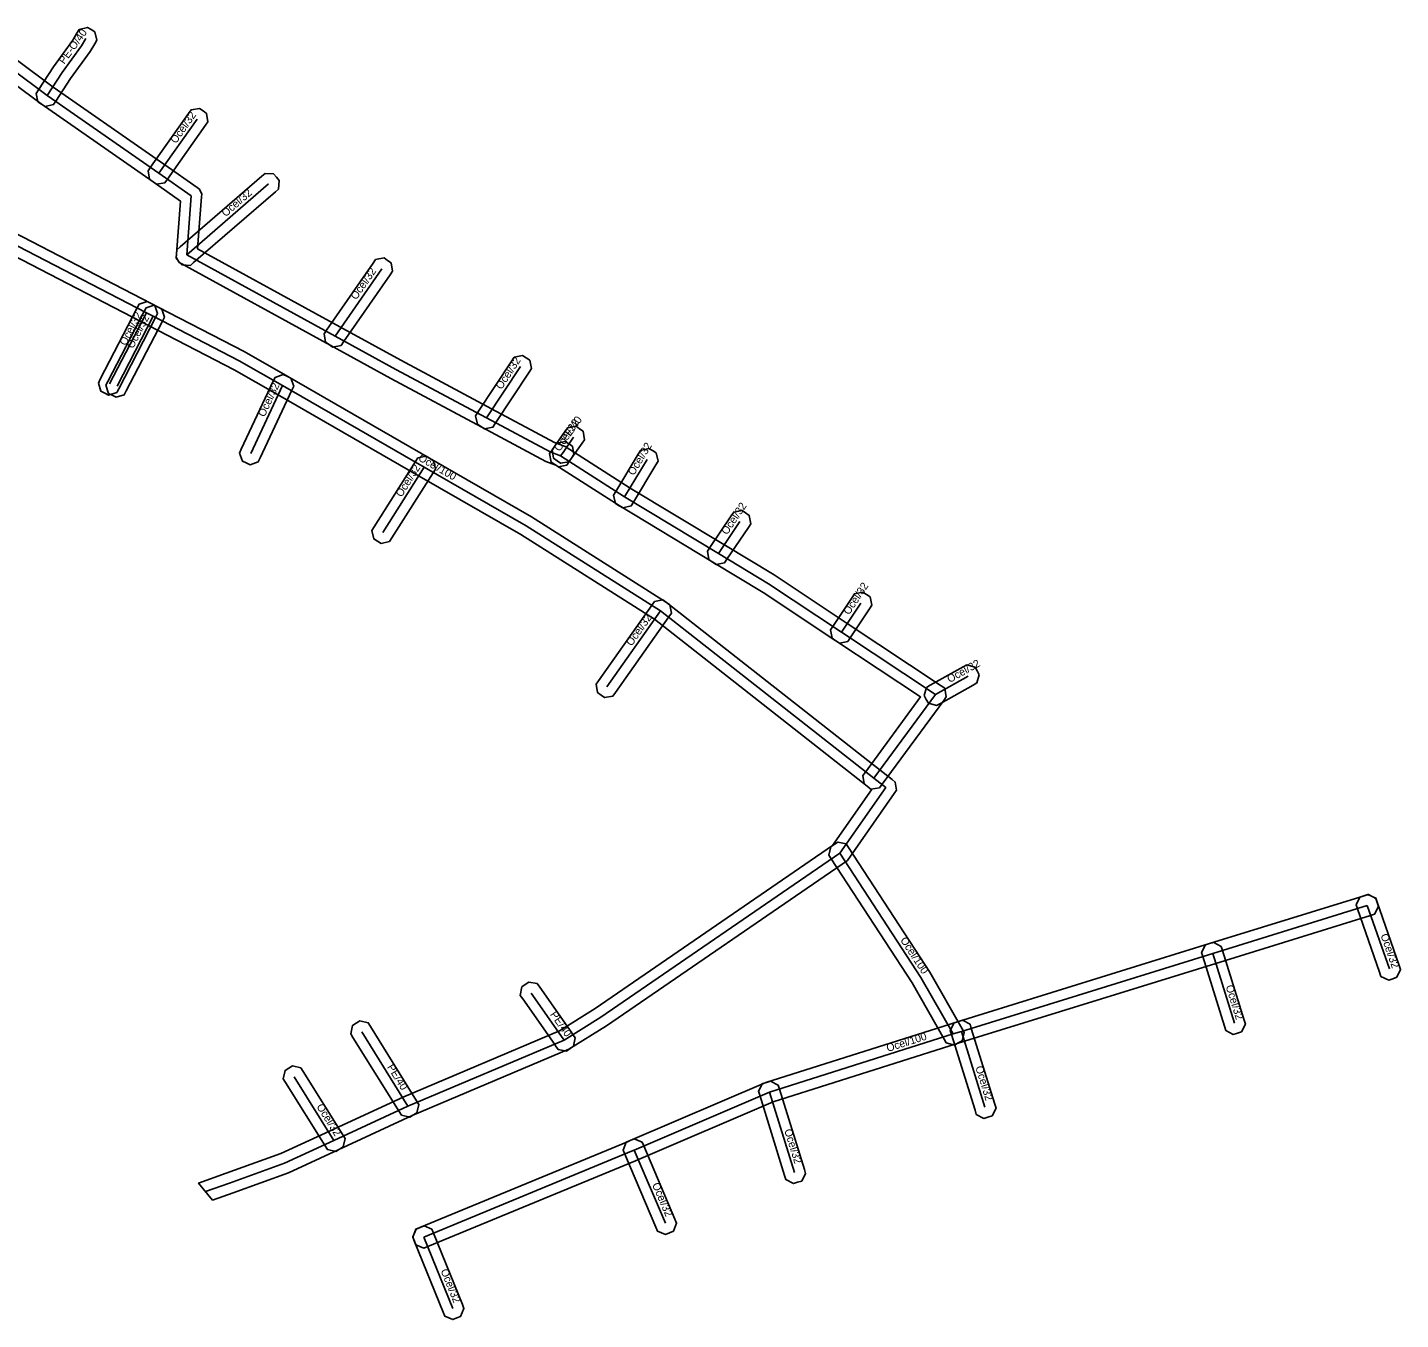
# Model space of a CAD drawing. Extents: x -588157 to -587884, y -1179022 to -1178805.
# Drawn here: x -588016.9 to -587884.2, y -1179022.3 to -1178897.4 of the extents above; entities that cross this region are included whole.
import ezdxf

# ---------------------------------------------------------------- set-up
doc = ezdxf.new("R2010")
doc.units = 0
for name, color, linetype in [('1', 7, 'Continuous'), ('14', 7, 'Continuous'), ('20', 7, 'Continuous')]:
    doc.layers.add(name, color=color, linetype=linetype)

msp = doc.modelspace()

# ---------------------------------------------------------------- linework, layer by layer
at = {"layer": '1'}
for points in [[(-588016.024, -1178903.821), (-588015.798, -1178903.474), (-588014.345, -1178901.244), (-588012.486, -1178898.669), (-588012.087, -1178898.006), (-588011.874, -1178897.651), (-588011.071, -1178897.45), (-588010.716, -1178897.663), (-588010.361, -1178897.876), (-588010.16, -1178898.679), (-588010.373, -1178899.034), (-588010.814, -1178899.771), (-588012.695, -1178902.376), (-588014.122, -1178904.566), (-588014.348, -1178904.913), (-588015.159, -1178905.084), (-588015.506, -1178904.858), (-588015.853, -1178904.632)], [(-588005.216, -1178911.301), (-588004.977, -1178910.963), (-588001.297, -1178905.753), (-588001.058, -1178905.415), (-588000.241, -1178905.274), (-587999.903, -1178905.513), (-587999.565, -1178905.752), (-587999.424, -1178906.569), (-587999.663, -1178906.907), (-588003.343, -1178912.117), (-588003.582, -1178912.455), (-588004.399, -1178912.596), (-588004.737, -1178912.357), (-588005.075, -1178912.118)], [(-588002.438, -1178918.935), (-588002.125, -1178918.664), (-587994.225, -1178911.824), (-587993.912, -1178911.553), (-587993.085, -1178911.612), (-587992.814, -1178911.925), (-587992.543, -1178912.238), (-587992.602, -1178913.065), (-587992.915, -1178913.336), (-588000.815, -1178920.176), (-588001.128, -1178920.447), (-588001.955, -1178920.388), (-588002.226, -1178920.075), (-588002.497, -1178919.762)], [(-587988.208, -1178927.049), (-587987.971, -1178926.709), (-587983.461, -1178920.219), (-587983.225, -1178919.879), (-587982.409, -1178919.732), (-587982.069, -1178919.969), (-587981.729, -1178920.205), (-587981.582, -1178921.021), (-587981.819, -1178921.361), (-587986.329, -1178927.851), (-587986.565, -1178928.191), (-587987.381, -1178928.338), (-587987.721, -1178928.101), (-587988.061, -1178927.865)], [(-588010.018, -1178931.819), (-588009.828, -1178931.451), (-588006.268, -1178924.561), (-588006.078, -1178924.193), (-588005.289, -1178923.942), (-588004.921, -1178924.132), (-588004.553, -1178924.322), (-588004.302, -1178925.111), (-588004.492, -1178925.479), (-588008.052, -1178932.369), (-588008.242, -1178932.737), (-588009.031, -1178932.988), (-588009.399, -1178932.798), (-588009.767, -1178932.608)], [(-588009.289, -1178932.027), (-588009.098, -1178931.66), (-588005.598, -1178924.91), (-588005.407, -1178924.542), (-588004.617, -1178924.291), (-588004.25, -1178924.482), (-588003.882, -1178924.673), (-588003.631, -1178925.463), (-588003.822, -1178925.83), (-588007.322, -1178932.58), (-588007.513, -1178932.948), (-588008.303, -1178933.199), (-588008.67, -1178933.008), (-588009.038, -1178932.817)], [(-587973.563, -1178934.986), (-587973.335, -1178934.64), (-587970.065, -1178929.67), (-587969.838, -1178929.324), (-587969.026, -1178929.157), (-587968.68, -1178929.385), (-587968.334, -1178929.612), (-587968.167, -1178930.424), (-587968.395, -1178930.77), (-587971.665, -1178935.74), (-587971.892, -1178936.086), (-587972.704, -1178936.253), (-587973.05, -1178936.025), (-587973.396, -1178935.798)], [(-587996.381, -1178938.591), (-587996.205, -1178938.216), (-587993.125, -1178931.646), (-587992.949, -1178931.271), (-587992.171, -1178930.989), (-587991.796, -1178931.165), (-587991.421, -1178931.341), (-587991.139, -1178932.119), (-587991.315, -1178932.494), (-587994.395, -1178939.064), (-587994.571, -1178939.439), (-587995.349, -1178939.721), (-587995.724, -1178939.545), (-587996.099, -1178939.369)], [(-587966.176, -1178938.282), (-587965.937, -1178937.944), (-587964.907, -1178936.484), (-587964.668, -1178936.145), (-587963.852, -1178936.004), (-587963.514, -1178936.243), (-587963.175, -1178936.482), (-587963.034, -1178937.298), (-587963.273, -1178937.636), (-587964.303, -1178939.096), (-587964.542, -1178939.435), (-587965.358, -1178939.576), (-587965.696, -1178939.337), (-587966.035, -1178939.098)], [(-587966.41, -1178938.643), (-587966.178, -1178938.3), (-587965.948, -1178937.96), (-587965.716, -1178937.617), (-587964.903, -1178937.46), (-587964.56, -1178937.692), (-587964.217, -1178937.924), (-587964.06, -1178938.737), (-587964.292, -1178939.08), (-587964.522, -1178939.42), (-587964.754, -1178939.763), (-587965.567, -1178939.92), (-587965.91, -1178939.688), (-587966.253, -1178939.456)], [(-587983.587, -1178946.075), (-587983.365, -1178945.725), (-587979.365, -1178939.415), (-587979.143, -1178939.065), (-587978.335, -1178938.883), (-587977.985, -1178939.105), (-587977.635, -1178939.327), (-587977.453, -1178940.135), (-587977.675, -1178940.485), (-587981.675, -1178946.795), (-587981.897, -1178947.145), (-587982.705, -1178947.327), (-587983.055, -1178947.105), (-587983.405, -1178946.883)], [(-587960.24, -1178942.658), (-587960.026, -1178942.303), (-587957.846, -1178938.693), (-587957.632, -1178938.338), (-587956.828, -1178938.14), (-587956.473, -1178938.354), (-587956.118, -1178938.568), (-587955.92, -1178939.372), (-587956.134, -1178939.727), (-587958.314, -1178943.337), (-587958.528, -1178943.692), (-587959.332, -1178943.89), (-587959.687, -1178943.676), (-587960.042, -1178943.462)], [(-587951.171, -1178948.073), (-587950.939, -1178947.73), (-587948.859, -1178944.65), (-587948.627, -1178944.307), (-587947.813, -1178944.149), (-587947.47, -1178944.381), (-587947.127, -1178944.613), (-587946.969, -1178945.427), (-587947.201, -1178945.77), (-587949.281, -1178948.85), (-587949.513, -1178949.193), (-587950.327, -1178949.351), (-587950.67, -1178949.119), (-587951.013, -1178948.887)], [(-587939.272, -1178955.682), (-587939.043, -1178955.337), (-587937.183, -1178952.537), (-587936.954, -1178952.192), (-587936.142, -1178952.028), (-587935.797, -1178952.257), (-587935.452, -1178952.486), (-587935.288, -1178953.298), (-587935.517, -1178953.643), (-587937.377, -1178956.443), (-587937.606, -1178956.788), (-587938.418, -1178956.952), (-587938.763, -1178956.723), (-587939.108, -1178956.494)], [(-587961.926, -1178960.932), (-587961.687, -1178960.594), (-587956.517, -1178953.264), (-587956.278, -1178952.925), (-587955.462, -1178952.784), (-587955.124, -1178953.023), (-587954.785, -1178953.262), (-587954.644, -1178954.078), (-587954.883, -1178954.416), (-587960.053, -1178961.746), (-587960.292, -1178962.085), (-587961.108, -1178962.226), (-587961.446, -1178961.987), (-587961.785, -1178961.748)], [(-587929.99, -1178961.239), (-587929.628, -1178961.037), (-587926.458, -1178959.267), (-587926.096, -1178959.065), (-587925.299, -1178959.29), (-587925.097, -1178959.652), (-587924.895, -1178960.014), (-587925.12, -1178960.811), (-587925.482, -1178961.013), (-587928.652, -1178962.783), (-587929.014, -1178962.985), (-587929.811, -1178962.76), (-587930.013, -1178962.398), (-587930.215, -1178962.036)], [(-587928.083, -1178995.596), (-587928.288, -1178995.236), (-587931.394, -1178989.801), (-587939.198, -1178977.795), (-587939.424, -1178977.448), (-587939.252, -1178976.638), (-587938.905, -1178976.412), (-587938.558, -1178976.186), (-587937.748, -1178976.358), (-587937.522, -1178976.705), (-587929.686, -1178988.759), (-587926.552, -1178994.244), (-587926.347, -1178994.604), (-587926.564, -1178995.403), (-587926.924, -1178995.608), (-587927.284, -1178995.813)], [(-587979.325, -1179013.604), (-587978.942, -1179013.446), (-587958.904, -1179005.161), (-587958.64, -1179005.043), (-587945.509, -1178999.431), (-587927.72, -1178993.786), (-587926.917, -1178993.535), (-587902.636, -1178986.005), (-587887.696, -1178981.375), (-587887.3, -1178981.252), (-587886.568, -1178981.638), (-587886.445, -1178982.034), (-587886.322, -1178982.43), (-587886.708, -1178983.162), (-587887.104, -1178983.285), (-587902.044, -1178987.915), (-587926.323, -1178995.445), (-587927.12, -1178995.694), (-587944.811, -1179001.309), (-587957.84, -1179006.877), (-587958.116, -1179006.999), (-587978.178, -1179015.294), (-587978.561, -1179015.452), (-587979.326, -1179015.135), (-587979.484, -1179014.752), (-587979.642, -1179014.369)], [(-587886.592, -1178981.61), (-587886.456, -1178982.001), (-587884.326, -1178988.121), (-587884.19, -1178988.512), (-587884.55, -1178989.258), (-587884.941, -1178989.394), (-587885.332, -1178989.53), (-587886.078, -1178989.17), (-587886.214, -1178988.779), (-587888.344, -1178982.659), (-587888.48, -1178982.268), (-587888.12, -1178981.522), (-587887.729, -1178981.386), (-587887.338, -1178981.25)], [(-587901.508, -1178986.268), (-587901.385, -1178986.664), (-587899.295, -1178993.404), (-587899.172, -1178993.8), (-587899.558, -1178994.532), (-587899.954, -1178994.655), (-587900.35, -1178994.778), (-587901.082, -1178994.392), (-587901.205, -1178993.996), (-587903.295, -1178987.256), (-587903.418, -1178986.86), (-587903.032, -1178986.128), (-587902.636, -1178986.005), (-587902.24, -1178985.882)], [(-587967.607, -1178989.867), (-587967.37, -1178990.207), (-587964.279, -1178994.629), (-587964.188, -1178994.761), (-587963.952, -1178995.101), (-587964.101, -1178995.916), (-587964.441, -1178996.152), (-587964.781, -1178996.388), (-587965.596, -1178996.239), (-587965.832, -1178995.899), (-587965.921, -1178995.771), (-587969.01, -1178991.353), (-587969.247, -1178991.013), (-587969.103, -1178990.197), (-587968.763, -1178989.96), (-587968.423, -1178989.723)], [(-587980.741, -1179002.6), (-587980.959, -1179002.248), (-587985.419, -1178995.068), (-587985.638, -1178994.716), (-587985.45, -1178993.909), (-587985.098, -1178993.691), (-587984.746, -1178993.472), (-587983.939, -1178993.66), (-587983.721, -1178994.012), (-587979.261, -1179001.192), (-587979.042, -1179001.544), (-587979.23, -1179002.351), (-587979.582, -1179002.569), (-587979.934, -1179002.788)], [(-587925.788, -1178993.798), (-587925.665, -1178994.194), (-587923.395, -1179001.524), (-587923.272, -1179001.92), (-587923.658, -1179002.652), (-587924.054, -1179002.775), (-587924.45, -1179002.898), (-587925.182, -1179002.512), (-587925.305, -1179002.116), (-587927.575, -1178994.786), (-587927.698, -1178994.39), (-587927.312, -1178993.658), (-587926.916, -1178993.535), (-587926.52, -1178993.412)], [(-587990.462, -1178998.009), (-587990.242, -1178998.36), (-587986.402, -1179004.5), (-587986.182, -1179004.851), (-587986.369, -1179005.658), (-587986.72, -1179005.878), (-587987.071, -1179006.098), (-587987.878, -1179005.911), (-587988.098, -1179005.56), (-587991.938, -1178999.42), (-587992.158, -1178999.069), (-587991.971, -1178998.262), (-587991.62, -1178998.042), (-587991.269, -1178997.822)], [(-587944.328, -1178999.677), (-587944.205, -1179000.073), (-587941.795, -1179007.823), (-587941.672, -1179008.219), (-587942.057, -1179008.952), (-587942.453, -1179009.075), (-587942.849, -1179009.198), (-587943.582, -1179008.813), (-587943.705, -1179008.417), (-587946.115, -1179000.667), (-587946.238, -1179000.271), (-587945.853, -1178999.538), (-587945.457, -1178999.415), (-587945.061, -1178999.292)], [(-587957.483, -1179005.186), (-587957.32, -1179005.567), (-587954.3, -1179012.637), (-587954.138, -1179013.018), (-587954.446, -1179013.787), (-587954.827, -1179013.95), (-587955.208, -1179014.112), (-587955.977, -1179013.804), (-587956.14, -1179013.423), (-587959.16, -1179006.353), (-587959.322, -1179005.972), (-587959.014, -1179005.203), (-587958.633, -1179005.04), (-587958.252, -1179004.878)], [(-587977.788, -1179013.611), (-587977.633, -1179013.995), (-587974.843, -1179020.885), (-587974.688, -1179021.269), (-587975.011, -1179022.032), (-587975.395, -1179022.187), (-587975.779, -1179022.342), (-587976.542, -1179022.019), (-587976.697, -1179021.635), (-587979.487, -1179014.745), (-587979.642, -1179014.361), (-587979.319, -1179013.598), (-587978.935, -1179013.443), (-587978.551, -1179013.288)]]:
    msp.add_lwpolyline(points, close=True, dxfattribs=at)
for points in [[(-588017.966, -1178900.543), (-588014.376, -1178903.208), (-588003.586, -1178910.721), (-588000.472, -1178912.924), (-588000.257, -1178913.076), (-588000.033, -1178913.552), (-588000.053, -1178913.814), (-588000.425, -1178918.853), (-587986.669, -1178926.403), (-587980.794, -1178929.621), (-587972.028, -1178934.309), (-587965.957, -1178937.567), (-587964.901, -1178937.96), (-587958.642, -1178941.971), (-587949.593, -1178947.434), (-587944.715, -1178950.375), (-587937.657, -1178955.057), (-587928.587, -1178961.077), (-587928.23, -1178961.314), (-587928.155, -1178961.736), (-587928.081, -1178962.158), (-587928.335, -1178962.503), (-587934.295, -1178970.603), (-587934.54, -1178970.936), (-587935.359, -1178971.061), (-587935.693, -1178970.815), (-587936.026, -1178970.57), (-587936.151, -1178969.751), (-587935.905, -1178969.417), (-587930.568, -1178962.163), (-587938.763, -1178956.723), (-587945.785, -1178952.065), (-587950.627, -1178949.146), (-587959.698, -1178943.669), (-587965.799, -1178939.76), (-587966.783, -1178939.393), (-587972.972, -1178936.071), (-587981.746, -1178931.379), (-587987.631, -1178928.157), (-588001.951, -1178920.297), (-588002.209, -1178920.155), (-588002.489, -1178919.639), (-588002.467, -1178919.346), (-588002.089, -1178914.23), (-588004.734, -1178912.359), (-588015.544, -1178904.832), (-588019.14, -1178902.163)], [(-588020.06, -1178916.302), (-588004.919, -1178924.133), (-588004.249, -1178924.483), (-587995.931, -1178928.782), (-587991.721, -1178931.203), (-587978.021, -1178939.083), (-587968.173, -1178944.754), (-587955.122, -1178953.022), (-587934.481, -1178969.225), (-587933.319, -1178970.147), (-587933.008, -1178970.393), (-587932.893, -1178971.178), (-587933.121, -1178971.503), (-587937.644, -1178977.972), (-587960.922, -1178993.957), (-587964.547, -1178996.22), (-587979.705, -1179002.634), (-587986.83, -1179005.938), (-587991.64, -1179008.156), (-587997.002, -1179010.091), (-587998.987, -1179010.799), (-587998.993, -1179010.791), (-588000.331, -1179009.155), (-587997.678, -1179008.209), (-587992.4, -1179006.304), (-587987.67, -1179004.122), (-587980.515, -1179000.806), (-587965.473, -1178994.44), (-587962.018, -1178992.283), (-587939.076, -1178976.528), (-587935.299, -1178971.128), (-587935.719, -1178970.795), (-587956.278, -1178954.658), (-587969.207, -1178946.466), (-587979.019, -1178940.817), (-587992.719, -1178932.937), (-587996.889, -1178930.538), (-588005.171, -1178926.257), (-588005.841, -1178925.907), (-588020.98, -1178918.078)]]:
    msp.add_lwpolyline(points, dxfattribs=at)
at = {"layer": '14'}
for points in [[(-588014.96, -1178904.02), (-588013.52, -1178901.81), (-588011.65, -1178899.22), (-588011.23, -1178898.52)], [(-587935.1, -1178970.01), (-587929.14, -1178961.91), (-587938.21, -1178955.89), (-587945.25, -1178951.22), (-587950.11, -1178948.29), (-587959.17, -1178942.82), (-587965.35, -1178938.86), (-587966.37, -1178938.48), (-587972.5, -1178935.19), (-587981.27, -1178930.5), (-587987.15, -1178927.28), (-588001.47, -1178919.42), (-588001.05, -1178913.74), (-588004.16, -1178911.54), (-588014.96, -1178904.02), (-588018.553, -1178901.353)], [(-588004.16, -1178911.54), (-588000.48, -1178906.33)], [(-588001.47, -1178919.42), (-587993.57, -1178912.58)], [(-587999.659, -1179009.977), (-587997.34, -1179009.15), (-587992.02, -1179007.23), (-587987.25, -1179005.03), (-587980.11, -1179001.72), (-587965.01, -1178995.33), (-587961.47, -1178993.12), (-587938.36, -1178977.25), (-587933.94, -1178970.93), (-587935.1, -1178970.01), (-587955.7, -1178953.84), (-587968.69, -1178945.61), (-587978.52, -1178939.95), (-587992.22, -1178932.07), (-587996.41, -1178929.66), (-588004.71, -1178925.37), (-588005.38, -1178925.02), (-588020.52, -1178917.19)], [(-587987.15, -1178927.28), (-587982.64, -1178920.79)], [(-588008.94, -1178931.91), (-588005.38, -1178925.02)], [(-588008.21, -1178932.12), (-588004.71, -1178925.37)], [(-587972.5, -1178935.19), (-587969.23, -1178930.22)], [(-587995.3, -1178938.64), (-587992.22, -1178932.07)], [(-587965.12, -1178938.52), (-587964.09, -1178937.06)], [(-587965.35, -1178938.86), (-587965.12, -1178938.52)], [(-587982.52, -1178946.26), (-587978.52, -1178939.95)], [(-587959.17, -1178942.82), (-587956.99, -1178939.21)], [(-587950.11, -1178948.29), (-587948.03, -1178945.21)], [(-587938.21, -1178955.89), (-587936.35, -1178953.09)], [(-587960.87, -1178961.17), (-587955.7, -1178953.84)], [(-587929.14, -1178961.91), (-587925.97, -1178960.14)], [(-587927.42, -1178994.74), (-587930.54, -1178989.28), (-587938.36, -1178977.25)], [(-587978.56, -1179014.37), (-587958.51, -1179006.08), (-587958.24, -1179005.96), (-587945.16, -1179000.37), (-587927.42, -1178994.74), (-587926.62, -1178994.49), (-587902.34, -1178986.96), (-587887.4, -1178982.33)], [(-587887.4, -1178982.33), (-587885.27, -1178988.45)], [(-587902.34, -1178986.96), (-587900.25, -1178993.7)], [(-587968.19, -1178990.78), (-587965.1, -1178995.2), (-587965.01, -1178995.33)], [(-587980.11, -1179001.72), (-587984.57, -1178994.54)], [(-587926.62, -1178994.49), (-587924.35, -1179001.82)], [(-587991.09, -1178998.89), (-587987.25, -1179005.03)], [(-587945.16, -1179000.37), (-587942.75, -1179008.12)], [(-587958.24, -1179005.96), (-587955.22, -1179013.03)], [(-587978.56, -1179014.37), (-587975.77, -1179021.26)]]:
    msp.add_lwpolyline(points, dxfattribs=at)

# ---------------------------------------------------------------- texts
at = {"layer": '20'}
for s, rotation, p in [('PE-O/40', 54.17042, (-588013.318, -1178901.053)), ('Ocel/32', 54.76514, (-588002.52, -1178908.735)), ('Ocel/32', 40.88676, (-587997.72, -1178915.8)), ('Ocel/32', 55.20397, (-587985.095, -1178923.835)), ('Ocel/32', 62.67501, (-588007.36, -1178928.265)), ('Ocel/32', 62.59242, (-588006.66, -1178928.545)), ('Ocel/32', 56.65718, (-587971.065, -1178932.505)), ('Ocel/32', 64.88293, (-587993.96, -1178935.155)), ('PE/40', 54.79782, (-587964.805, -1178937.59)), ('Ocel/32', 55.9228, (-587965.435, -1178938.49)), ('Ocel/32', 58.87314, (-587958.28, -1178940.815)), ('Ocel/100', 330.09324, (-587979.175, -1178939.258)), ('Ocel/32', 57.6288, (-587980.72, -1178942.905)), ('Ocel/32', 55.96787, (-587949.27, -1178946.55)), ('Ocel/32', 56.40448, (-587937.48, -1178954.29)), ('Ocel/32', 54.80389, (-587958.485, -1178957.305)), ('Ocel/32', 29.17723, (-587927.755, -1178960.825)), ('Ocel/100', 303.02554, (-587932.564, -1178985.659)), ('Ocel/32', 289.1899, (-587886.135, -1178985.19)), ('Ocel/32', 287.22809, (-587901.095, -1178990.13)), ('PE/40', 304.95721, (-587966.4, -1178992.855)), ('Ocel/100', 17.60745, (-587933.734, -1178996.48)), ('PE/40', 301.84731, (-587982.14, -1178997.93)), ('Ocel/32', 287.20703, (-587925.285, -1178997.955)), ('Ocel/32', 302.02216, (-587988.97, -1179001.76)), ('Ocel/32', 287.27401, (-587943.755, -1179004.045)), ('Ocel/32', 293.13009, (-587956.53, -1179009.295)), ('Ocel/32', 292.04473, (-587976.965, -1179017.615))]:
    msp.add_text(s, height=0.75, rotation=rotation, dxfattribs=at).set_placement(p)

doc.saveas('drawing.dxf')
